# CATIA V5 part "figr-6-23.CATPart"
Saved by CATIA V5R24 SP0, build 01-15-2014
Part number: Part1
Bounding box of the stored display mesh (mm): x 0 to 150, y -70 to 70, z -150 to 69.968
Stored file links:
  D:\KAVITA\CATIA V5-6R2014 Project_ Kavita\CATIA V5-6R2014_partfiles\Partfiles\c06_catia_v5-6r2014_prt\figr-6-23.CATPart
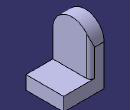
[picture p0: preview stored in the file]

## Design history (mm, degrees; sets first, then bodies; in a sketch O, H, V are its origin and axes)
Body1 (main body)
  Sketch1 on yz-plane, origin (0, 0, 0), H (0, 1, 0), V (0, 0, 1)
    arc A1 centre (0, 0) radius 70 from (70, 0) to (-70, 0) ccw
    point P1 (70, 0)
    point P2 (-70, 0)
    line L1 (-70, 0) -> (-70, -150)
    line L2 (-70, -150) -> (70, -150)
    line L3 (70, -150) -> (70, 0)
    construction circle A2 centre (0, 0) radius 37.5
    radius A1 = 70
    radius A2 = 37.5
    distance O L2 = 150
    coincidence: P1 H, P2 H
    tangency: L1 A1, L3 A1
    horizontal: L2 H
  Pad1: profile Sketch1, direction (1, 0, 0), length 50
  Sketch2 on face of Pad1, origin (50, 0, 0), H (0, 1, 0), V (0, 0, 1)
    line L1 (-70, -150) -> (70, -150)
    line L2 (70, -150) -> (70, -100)
    line L3 (70, -100) -> (-70, -100)
    line L4 (-70, -100) -> (-70, -150)
    reference projected line E1 (-70, -150) -> (70, -150) from edge [face of Pad1 | face of Pad1]
    reference projected line E2 (-70, 0) -> (-70, -150) from edge [face of Pad1 | face of Pad1]
    reference projected line E3 (70, -150) -> (70, 0) from edge [face of Pad1 | face of Pad1]
    length L2 = 50
    horizontal: L1 H, L3 H
    vertical: L2 V, L4 V
    coincidence: L1 E1, E2 L4, L2 E3
  Pad2: profile Sketch2, direction (1, 0, 0), length 100
  Fillet1: radius 15, on edge [face of Pad2 | end face of Pad1]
